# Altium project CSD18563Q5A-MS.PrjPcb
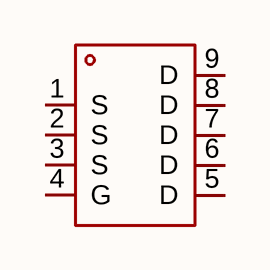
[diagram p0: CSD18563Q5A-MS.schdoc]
1 sheet, 1 parts. Net scope: global (net labels, ports and power ports of the same name join across sheets).

## Sheet CSD18563Q5A-MS.schdoc
size 127 x 101 mm

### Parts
Q?  csd18563q5a-ms  [PDFN-8_L4.9-W5.8-P1.27-LS6.1-BL]  (value not drawn)

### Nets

Not connected (* = marked no-connect by the designer): Q? 1(S) 2(S) 3(S) 4(G) 5(D) 6(D) 7(D) 8(D) 9(D)

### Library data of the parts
Q? = csd18563q5a-ms: 数量:1个N沟道;漏源电压(Vdss):60V;连续漏极电流(Id):80A;导通电阻(RDS(on)):5.3mΩ@10V;耗散功率(Pd):108W;阈值电压(Vgs(th)):3V;; Manufacturer: MSKSEMI(美森科); AddInBom: yes; ModelId: 178189b27e7544aca50c111426555358; ModelName: PDFN-8_L4.9-W5.8-H1.0-P1.27; ModelTransform: 200.787,240.157,0,0,0,0,-0.097,0,0; Number: 1个N沟道; Drain to Source Voltage: 60V; Current - Continuous Drain(Id): 80A; Pd - Power Dissipation: 108W; Gate Threshold Voltage (Vgs(th)): 3V; Gate Charge(Qg): 90nC; Input Capacitance(Ciss): 4.136nF; Reverse Transfer Capacitance (Crss@Vds): 257pF; Type: N沟道; Output Capacitance(Coss): 286pF; Vgs: ±20V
